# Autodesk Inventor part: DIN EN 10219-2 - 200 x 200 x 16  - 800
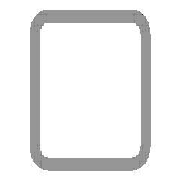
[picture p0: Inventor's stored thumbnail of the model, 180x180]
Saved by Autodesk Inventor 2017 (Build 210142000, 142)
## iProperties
Created: 2017-11
Part Number: DIN EN 10219-2 - 200 x 200 x 16  - 800
Material: Steel, Mild
Description: Cold formed welded structural hollow sections of non-alloy and fine grain structural steel
Document SubType Name: Modeling
Standard: DIN
Designer: iusti
Standard Revision: 2006-07
Standards Organization: DIN
Language: en-US
Size Designation: 200 x 200 x 16
Categories: <MemberInstance><Categories><Category DisplayName="Structural Shapes" InternalName="089c4875-fa83-4c05-b084-43b9cc11f5ed" Mnemonic="GRDR"><CategoryParameter Dis
Stock Number: 200 x 200 x 16
Mass: 67053.1 g
Surface Area: 10890.8 cm^2
Volume: 8541.79 cm^3
Density: 7.85 g/cm^3
Appearance: Semi-Polished
IsCustomPart: 1
_CCFamilyMember: 103
_CCFamilyDisplayName: DIN EN 10219-2 (Square Hollow Section - Cold Formed) - Cold formed welded structural hollow sections of non-alloy and fine grain structural steel
_FrameMemberDoc: Frame Member File
_Version: 15.0.0
_GetPNFromCC: 1
Author: iusti
G_L: 800.000 mm
G_W: 200.000 mm
G_H: 200.000 mm
+022A92A4-1665-4D87-A3CD-3B04628A670A+CUTDETAIL1: Cut
+D7EF0BB8-D807-4400-82D5-9F9535CAC881+CUTDETAIL2: Cut
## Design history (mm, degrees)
node "Start plane"
node "End plane"
sketch "Sketch"
  geometry: L1 (-100, -52)-(-100, 52); L2 (-52, 100)-(52, 100); L3 (100, 52)-(100, -52); L4 (52, -100)-(-52, -100); L5 (-52, 84)-(52, 84); L6 (84, 52)-(84, -52); L7 (52, -84)-(-52, -84); L8 (-84, -52)-(-84, 52); L9 (0, 153.918)-(0, -153.918) reference; L10 (-153.918, 0)-(153.918, 0) reference; A1 r 48 centre (-52, -52) between (-100, -52) and (-52, -100); A2 r 48 centre (-52, 52) between (-52, 100) and (-100, 52); A3 r 48 centre (52, 52) between (100, 52) and (52, 100); A4 r 48 centre (52, -52) between (52, -100) and (100, -52); A5 r 32 centre (-52, 52) between (-52, 84) and (-84, 52); A6 r 32 centre (52, 52) between (84, 52) and (52, 84); A7 r 32 centre (52, -52) between (52, -84) and (84, -52); A8 r 32 centre (-52, -52) between (-84, -52) and (-52, -84)
  constraints: 16 end point, 16 point on circle, 8 centre point, 8 tangent, 4 parallel, 3 equal radius, 2 perpendicular, 7 other
  dimensions: "d7" = 48 radius of A1 (= G_IR); "d10" = 200 distance between parallel lines of L2 L4 (= G_H); "d11" = 200 distance between parallel lines of L1 L3 (= G_W); "d12" = 16 distance between parallel lines of L3 L6 (= G_T); "d15" = 100 distance between parallel lines of L2 L10 (= 0.5 x d10); "d16" = 100 distance between parallel lines of L9 L3 (= 0.5 x d11)
extrude "Body" new body sketch "Sketch" stored distance "d3" = 800 (= G_L); taper "d4" = 0 deg
node "Driven Length"
  sketch "Sketch3"
    geometry: L1 (0, 0)-(10, 0) reference
    constraints: 2 end point, 1 horizontal
  workplane "Work Plane3"
  sketch "Sketch4"
    geometry: L1 (-2, 100)-(12, 100) reference; L2 (-2, 900)-(12, 900) reference
    dimensions: "d18" = 800 distance between parallel lines of L1 L2 (derived)
workplane "Work Plane4"
split "Split1"
workplane "Work Plane5"
split "Split2"
body "Solid1"
other parameters: "G_W" = 200 [user parameter; used in 1 equation term], "G_H" = 200 [user parameter; used in 1 equation term], "G_T" = 16 [user parameter; used in 1 equation term], "G_IR" = 48 [user parameter; used in 1 equation term], "G_L" = 800 (= d18) [user parameter; used in 1 equation term], "d17" = 90 deg
